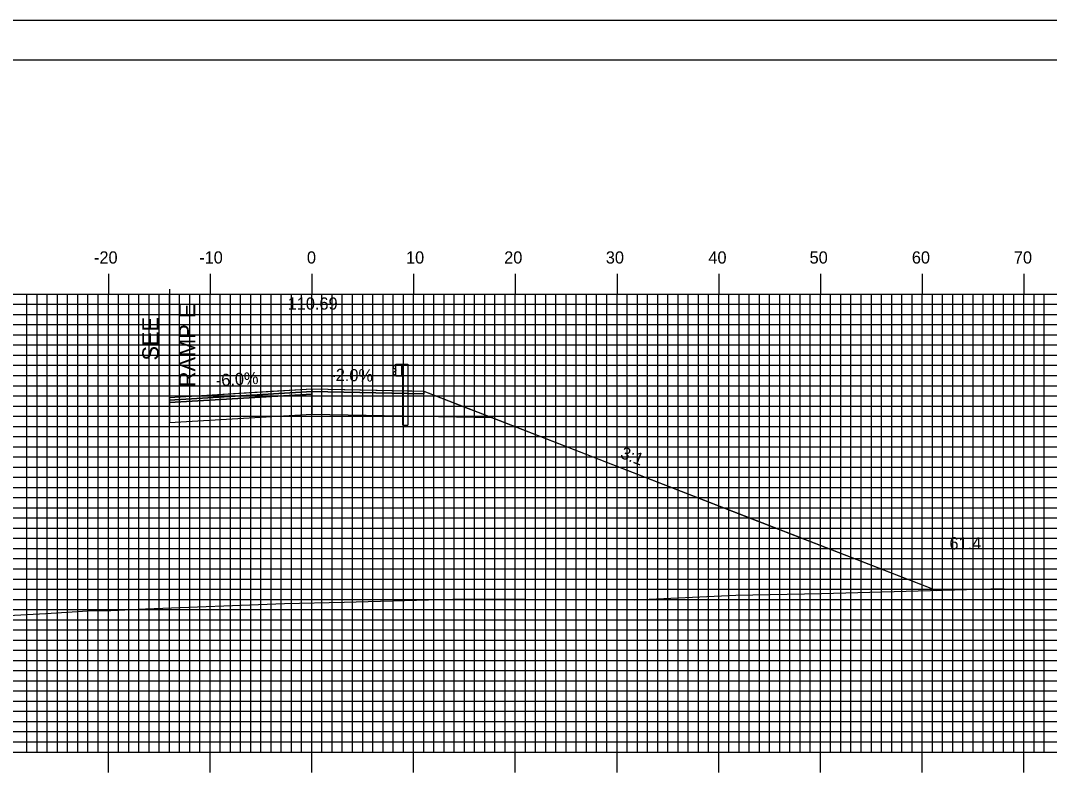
# Model space of a CAD drawing. Extents: x 485 to 829, y -1658 to -1438.
# Drawn here: x 622.5 to 723.6, y -1512.1 to -1437.7 of the extents above; entities that cross this region are included whole.
import ezdxf

# ---------------------------------------------------------------- set-up
doc = ezdxf.new("R2010")
doc.units = 0
for name, color, linetype in [('ANNOTATION', 7, 'Continuous'), ('BORDER', 7, 'Continuous'), ('D_Guardrail_Beam_Lt', 7, 'Continuous'), ('D_Roadway_Centerline', 7, 'Continuous'), ('D_Roadway_Centerline_Text', 7, 'Continuous'), ('D_Roadway_Edge_Shoulder', 7, 'Continuous'), ('D_Roadway_Edge_TW', 7, 'Continuous'), ('D_Roadway_Pavement', 7, 'Continuous'), ('D_Roadway_SlopeLines', 7, 'Continuous'), ('D_Roadway_SubGrade', 7, 'Continuous'), ('D_Text_Standard', 7, 'Continuous'), ('H_V ANNOTATION', 7, 'Continuous'), ('MAJOR', 7, 'Continuous'), ('MINOR', 7, 'Continuous'), ('PLOT BOUNDARY', 7, 'Continuous'), ('S_Roadway_Centerline', 7, 'Continuous')]:
    doc.layers.add(name, color=color, linetype=linetype)

msp = doc.modelspace()

# ---------------------------------------------------------------- linework, layer by layer
at = {"layer": 'BORDER'}
msp.add_lwpolyline([(501.53, -1651.6), (821.53, -1651.6), (821.53, -1441.6), (501.53, -1441.6)], close=True, dxfattribs=at)
at = {"layer": 'D_Guardrail_Beam_Lt'}
for p, q in [((659.31, -1471.6), (659.17, -1471.7)), ((659.17, -1471.84), (659.37, -1471.98)), ((659.37, -1472.18), (659.17, -1472.31)), ((659.17, -1472.46), (659.31, -1472.56)), ((659.4, -1471.58), (659.33, -1471.59)), ((659.4, -1471.49), (660.09, -1471.49)), ((659.4, -1472.66), (659.4, -1471.49)), ((659.4, -1472.04), (659.4, -1472.11)), ((659.93, -1471.49), (659.93, -1472.66)), ((660.03, -1471.49), (660.03, -1472.66)), ((660.09, -1471.49), (660.56, -1471.49)), ((660.09, -1471.49), (660.09, -1472.66)), ((660.56, -1471.49), (660.56, -1477.49)), ((659.33, -1472.56), (659.4, -1472.58)), ((660.09, -1472.66), (659.4, -1472.66)), ((660.07, -1477.49), (660.07, -1472.66)), ((660.07, -1477.49), (660.56, -1477.49))]:
    msp.add_line(p, q, dxfattribs=at)
for centre, major_axis, start_param, end_param in [((659.22, -1471.77), (-0.0877, 0), 5.323254, 7.243116), ((659.22, -1472.38), (-0.0877, 0), 5.323254, 7.243116), ((659.34, -1471.63), (-0.0417, 0), 4.907132, 5.323254), ((659.32, -1472.04), (0.0789, 0), 0, 0.959931), ((659.32, -1472.11), (0.0789, 0), 5.323254, 6.283185), ((659.34, -1472.52), (-0.0417, 0), 0.959931, 1.376053)]:
    msp.add_ellipse(centre, major_axis=major_axis, ratio=0.995501, start_param=start_param, end_param=end_param, dxfattribs=at)
at = {"layer": 'D_Roadway_Centerline'}
msp.add_lwpolyline([(637.13, -1474.76), (645.54, -1474.25), (651.13, -1473.92), (655.97, -1474.01), (659.13, -1474.08), (660.96, -1474.11), (662.13, -1474.14), (666.23, -1475.73), (668.93, -1476.77), (694.38, -1486.68), (712.58, -1493.72)], dxfattribs=at)
at = {"layer": 'D_Roadway_Edge_Shoulder'}
for points in [[(651.13, -1473.92), (659.13, -1474.08), (659.13, -1474.08), (662.13, -1474.14), (662.13, -1474.39), (651.13, -1474.17)], [(651.13, -1473.92), (662.13, -1474.14), (662.13, -1474.39), (651.13, -1474.17)]]:
    msp.add_lwpolyline(points, close=True, dxfattribs=at)
at = {"layer": 'D_Roadway_Edge_TW'}
msp.add_lwpolyline([(637.13, -1474.76), (651.13, -1473.92), (651.13, -1474.17), (637.13, -1475.01)], close=True, dxfattribs=at)
at = {"layer": 'D_Roadway_Pavement'}
msp.add_lwpolyline([(637.13, -1475.01), (651.13, -1474.17), (651.13, -1474.42), (637.13, -1475.26)], close=True, dxfattribs=at)
msp.add_lwpolyline([(651.13, -1474.17), (651.13, -1474.42)], dxfattribs=at)
msp.add_lwpolyline([(651.13, -1474.17), (651.13, -1474.42)], dxfattribs=at)
msp.add_lwpolyline([(651.13, -1474.17), (651.13, -1474.42)], dxfattribs=at)
at = {"layer": 'D_Roadway_SlopeLines'}
msp.add_lwpolyline([(662.13, -1474.14), (712.58, -1493.72)], dxfattribs=at)
msp.add_lwpolyline([(662.13, -1474.14), (712.58, -1493.72)], dxfattribs=at)
at = {"layer": 'D_Roadway_SubGrade'}
msp.add_line((637.13, -1464.12), (637.13, -1477.26), dxfattribs=at)
for points in [[(637.13, -1475.26), (651.13, -1474.42), (651.13, -1476.42), (637.13, -1477.26)], [(651.13, -1474.42), (651.13, -1474.17), (662.13, -1474.39), (662.13, -1474.14), (668.93, -1476.77), (651.13, -1476.42)]]:
    msp.add_lwpolyline(points, close=True, dxfattribs=at)
at = {"layer": 'MAJOR'}
for p, q in [((631.13, -1462.6), (631.13, -1464.6)), ((641.13, -1462.6), (641.13, -1464.6)), ((651.13, -1462.6), (651.13, -1464.6)), ((661.13, -1462.6), (661.13, -1464.6)), ((671.13, -1462.6), (671.13, -1464.6)), ((681.13, -1462.6), (681.13, -1464.6)), ((691.13, -1462.6), (691.13, -1464.6)), ((701.13, -1462.6), (701.13, -1464.6)), ((711.13, -1462.6), (711.13, -1464.6)), ((721.13, -1462.6), (721.13, -1464.6)), ((511.13, -1464.6), (791.13, -1464.6)), ((511.13, -1464.6), (791.13, -1464.6)), ((631.13, -1509.6), (631.13, -1464.6)), ((641.13, -1509.6), (641.13, -1464.6)), ((651.13, -1509.6), (651.13, -1464.6)), ((661.13, -1509.6), (661.13, -1464.6)), ((671.13, -1509.6), (671.13, -1464.6)), ((681.13, -1509.6), (681.13, -1464.6)), ((691.13, -1509.6), (691.13, -1464.6)), ((701.13, -1509.6), (701.13, -1464.6)), ((711.13, -1509.6), (711.13, -1464.6)), ((721.13, -1509.6), (721.13, -1464.6)), ((511.13, -1469.6), (791.13, -1469.6)), ((511.13, -1474.6), (791.13, -1474.6)), ((511.13, -1479.6), (791.13, -1479.6)), ((511.13, -1484.6), (791.13, -1484.6)), ((511.13, -1489.6), (791.13, -1489.6)), ((511.13, -1494.6), (791.13, -1494.6)), ((511.13, -1499.6), (791.13, -1499.6)), ((511.13, -1504.6), (791.13, -1504.6)), ((511.13, -1509.6), (791.13, -1509.6)), ((511.13, -1509.6), (791.13, -1509.6)), ((631.13, -1511.61), (631.13, -1509.6)), ((641.13, -1511.61), (641.13, -1509.6)), ((651.13, -1511.61), (651.13, -1509.6)), ((661.13, -1511.61), (661.13, -1509.6)), ((671.13, -1511.61), (671.13, -1509.6)), ((681.13, -1511.61), (681.13, -1509.6)), ((691.13, -1511.61), (691.13, -1509.6)), ((701.13, -1511.61), (701.13, -1509.6)), ((711.13, -1511.61), (711.13, -1509.6)), ((721.13, -1511.61), (721.13, -1509.6))]:
    msp.add_line(p, q, dxfattribs=at)
at = {"layer": 'MINOR'}
for p, q in [((623.13, -1509.6), (623.13, -1464.6)), ((624.13, -1509.6), (624.13, -1464.6)), ((625.13, -1509.6), (625.13, -1464.6)), ((626.13, -1509.6), (626.13, -1464.6)), ((627.13, -1509.6), (627.13, -1464.6)), ((628.13, -1509.6), (628.13, -1464.6)), ((629.13, -1509.6), (629.13, -1464.6)), ((630.13, -1509.6), (630.13, -1464.6)), ((632.13, -1509.6), (632.13, -1464.6)), ((633.13, -1509.6), (633.13, -1464.6)), ((634.13, -1509.6), (634.13, -1464.6)), ((635.13, -1509.6), (635.13, -1464.6)), ((636.13, -1509.6), (636.13, -1464.6)), ((637.13, -1509.6), (637.13, -1464.6)), ((638.13, -1509.6), (638.13, -1464.6)), ((639.13, -1509.6), (639.13, -1464.6)), ((640.13, -1509.6), (640.13, -1464.6)), ((642.13, -1509.6), (642.13, -1464.6)), ((643.13, -1509.6), (643.13, -1464.6)), ((644.13, -1509.6), (644.13, -1464.6)), ((645.13, -1509.6), (645.13, -1464.6)), ((646.13, -1509.6), (646.13, -1464.6)), ((647.13, -1509.6), (647.13, -1464.6)), ((648.13, -1509.6), (648.13, -1464.6)), ((649.13, -1509.6), (649.13, -1464.6)), ((650.13, -1509.6), (650.13, -1464.6)), ((652.13, -1509.6), (652.13, -1464.6)), ((653.13, -1509.6), (653.13, -1464.6)), ((654.13, -1509.6), (654.13, -1464.6)), ((655.13, -1509.6), (655.13, -1464.6)), ((656.13, -1509.6), (656.13, -1464.6)), ((657.13, -1509.6), (657.13, -1464.6)), ((658.13, -1509.6), (658.13, -1464.6)), ((659.13, -1509.6), (659.13, -1464.6)), ((660.13, -1509.6), (660.13, -1464.6)), ((662.13, -1509.6), (662.13, -1464.6)), ((663.13, -1509.6), (663.13, -1464.6)), ((664.13, -1509.6), (664.13, -1464.6)), ((665.13, -1509.6), (665.13, -1464.6)), ((666.13, -1509.6), (666.13, -1464.6)), ((667.13, -1509.6), (667.13, -1464.6)), ((668.13, -1509.6), (668.13, -1464.6)), ((669.13, -1509.6), (669.13, -1464.6)), ((670.13, -1509.6), (670.13, -1464.6)), ((672.13, -1509.6), (672.13, -1464.6)), ((673.13, -1509.6), (673.13, -1464.6)), ((674.13, -1509.6), (674.13, -1464.6)), ((675.13, -1509.6), (675.13, -1464.6)), ((676.13, -1509.6), (676.13, -1464.6)), ((677.13, -1509.6), (677.13, -1464.6)), ((678.13, -1509.6), (678.13, -1464.6)), ((679.13, -1509.6), (679.13, -1464.6)), ((680.13, -1509.6), (680.13, -1464.6)), ((682.13, -1509.6), (682.13, -1464.6)), ((683.13, -1509.6), (683.13, -1464.6)), ((684.13, -1509.6), (684.13, -1464.6)), ((685.13, -1509.6), (685.13, -1464.6)), ((686.13, -1509.6), (686.13, -1464.6)), ((687.13, -1509.6), (687.13, -1464.6)), ((688.13, -1509.6), (688.13, -1464.6)), ((689.13, -1509.6), (689.13, -1464.6)), ((690.13, -1509.6), (690.13, -1464.6)), ((692.13, -1509.6), (692.13, -1464.6)), ((693.13, -1509.6), (693.13, -1464.6)), ((694.13, -1509.6), (694.13, -1464.6)), ((695.13, -1509.6), (695.13, -1464.6)), ((696.13, -1509.6), (696.13, -1464.6)), ((697.13, -1509.6), (697.13, -1464.6)), ((698.13, -1509.6), (698.13, -1464.6)), ((699.13, -1509.6), (699.13, -1464.6)), ((700.13, -1509.6), (700.13, -1464.6)), ((702.13, -1509.6), (702.13, -1464.6)), ((703.13, -1509.6), (703.13, -1464.6)), ((704.13, -1509.6), (704.13, -1464.6)), ((705.13, -1509.6), (705.13, -1464.6)), ((706.13, -1509.6), (706.13, -1464.6)), ((707.13, -1509.6), (707.13, -1464.6)), ((708.13, -1509.6), (708.13, -1464.6)), ((709.13, -1509.6), (709.13, -1464.6)), ((710.13, -1509.6), (710.13, -1464.6)), ((712.13, -1509.6), (712.13, -1464.6)), ((713.13, -1509.6), (713.13, -1464.6)), ((714.13, -1509.6), (714.13, -1464.6)), ((715.13, -1509.6), (715.13, -1464.6)), ((716.13, -1509.6), (716.13, -1464.6)), ((717.13, -1509.6), (717.13, -1464.6)), ((718.13, -1509.6), (718.13, -1464.6)), ((719.13, -1509.6), (719.13, -1464.6)), ((720.13, -1509.6), (720.13, -1464.6)), ((722.13, -1509.6), (722.13, -1464.6)), ((723.13, -1509.6), (723.13, -1464.6)), ((511.13, -1465.6), (791.13, -1465.6)), ((511.13, -1466.6), (791.13, -1466.6)), ((511.13, -1467.6), (791.13, -1467.6)), ((511.13, -1468.6), (791.13, -1468.6)), ((511.13, -1470.6), (791.13, -1470.6)), ((511.13, -1471.6), (791.13, -1471.6)), ((511.13, -1472.6), (791.13, -1472.6)), ((511.13, -1473.6), (791.13, -1473.6)), ((511.13, -1475.6), (791.13, -1475.6)), ((511.13, -1476.6), (791.13, -1476.6)), ((511.13, -1477.6), (791.13, -1477.6)), ((511.13, -1478.6), (791.13, -1478.6)), ((511.13, -1480.6), (791.13, -1480.6)), ((511.13, -1481.6), (791.13, -1481.6)), ((511.13, -1482.6), (791.13, -1482.6)), ((511.13, -1483.6), (791.13, -1483.6)), ((511.13, -1485.6), (791.13, -1485.6)), ((511.13, -1486.6), (791.13, -1486.6)), ((511.13, -1487.6), (791.13, -1487.6)), ((511.13, -1488.6), (791.13, -1488.6)), ((511.13, -1490.6), (791.13, -1490.6)), ((511.13, -1491.6), (791.13, -1491.6)), ((511.13, -1492.6), (791.13, -1492.6)), ((511.13, -1493.6), (791.13, -1493.6)), ((511.13, -1495.6), (791.13, -1495.6)), ((511.13, -1496.6), (791.13, -1496.6)), ((511.13, -1497.6), (791.13, -1497.6)), ((511.13, -1498.6), (791.13, -1498.6)), ((511.13, -1500.6), (791.13, -1500.6)), ((511.13, -1501.6), (791.13, -1501.6)), ((511.13, -1502.6), (791.13, -1502.6)), ((511.13, -1503.6), (791.13, -1503.6)), ((511.13, -1505.6), (791.13, -1505.6)), ((511.13, -1506.6), (791.13, -1506.6)), ((511.13, -1507.6), (791.13, -1507.6)), ((511.13, -1508.6), (791.13, -1508.6))]:
    msp.add_line(p, q, dxfattribs=at)
at = {"layer": 'PLOT BOUNDARY'}
msp.add_lwpolyline([(485.35, -1657.72), (825.35, -1657.72), (825.35, -1437.72), (485.35, -1437.72)], close=True, dxfattribs=at)
at = {"layer": 'S_Roadway_Centerline'}
msp.add_lwpolyline([(616.3, -1496.46), (624.98, -1495.99), (629.65, -1495.69), (631.37, -1495.68), (634.77, -1495.54), (648.43, -1495.02), (654.32, -1494.89), (666.18, -1494.54), (672.13, -1494.58), (682.88, -1494.63), (692.81, -1494.19), (701.22, -1494.02), (717.87, -1493.58), (719.17, -1493.55), (731.05, -1493.68), (736.02, -1493.66), (744.54, -1493.54), (753.83, -1493.55), (763.95, -1493.4), (769.39, -1493.17), (771.76, -1493.11), (777.05, -1492.99), (789.2, -1492.93), (791.13, -1492.91)], dxfattribs=at)

# ---------------------------------------------------------------- texts
at = {"layer": 'ANNOTATION'}
for s, height, rotation, p in [('RAMP E', 1.6, 90, (639.67, -1473.75)), ('SEE', 1.6, 90, (636.07, -1471.13)), ('-6.0%', 1.2, 3.4336, (641.73, -1473.68)), ('-2.0%', 1.2, 358.8527, (652.94, -1473.12)), ('3:1', 1.2, 338.7355, (681.37, -1480.67))]:
    msp.add_text(s, height=height, rotation=rotation, dxfattribs=at).set_placement(p)
at = {"layer": 'D_Roadway_Centerline_Text'}
msp.add_text('110.69', height=1.2, dxfattribs=at).set_placement((648.76, -1466.13))
at = {"layer": 'D_Text_Standard'}
msp.add_text("61.4'", height=1.2, dxfattribs=at).set_placement((713.81, -1489.69))
at = {"layer": 'H_V ANNOTATION'}
for s, p in [('-20', (629.72, -1461.6)), ('-10', (640.06, -1461.6)), ('0', (650.65, -1461.6)), ('10', (660.39, -1461.6)), ('20', (670.04, -1461.6)), ('30', (680.03, -1461.6)), ('40', (690.11, -1461.6)), ('50', (700.06, -1461.6)), ('60', (710.11, -1461.6)), ('70', (720.14, -1461.6))]:
    msp.add_text(s, height=1.2, dxfattribs=at).set_placement(p)

doc.saveas('drawing.dxf')
